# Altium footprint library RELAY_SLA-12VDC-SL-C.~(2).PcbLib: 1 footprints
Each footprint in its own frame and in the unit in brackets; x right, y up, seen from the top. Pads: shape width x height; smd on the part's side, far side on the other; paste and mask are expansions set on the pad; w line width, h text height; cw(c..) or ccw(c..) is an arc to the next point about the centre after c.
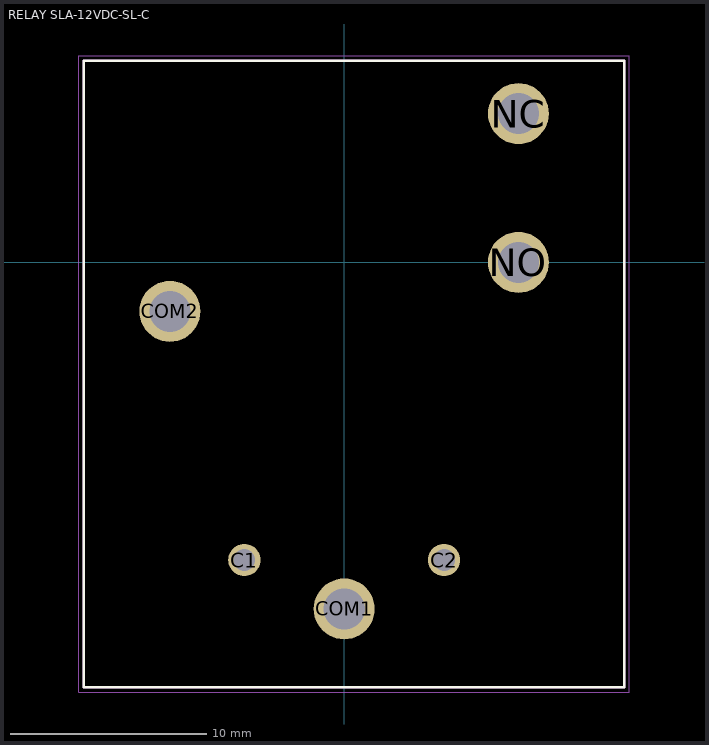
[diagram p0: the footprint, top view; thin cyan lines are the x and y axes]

## RELAY SLA-12VDC-SL-C [mm]
height 20.4
pads (6):
  round 1.65 hole 1.1: C1(-5.1,-15.2) C2(5.1,-15.2)
  round 3.116 hole 2.1: COM1(0,-17.7) COM2(-8.9,-2.5) NC(8.9,7.6) NO(8.9,0)
Top Overlay:
  lines w0.127: -13.3,-21.7 -13.3,10.3 14.3,10.3 14.3,-21.7 -13.3,-21.7
Assembly Top:
  lines w0.127: -13.3,-21.7 -13.3,10.3 14.3,10.3 14.3,-21.7 -13.3,-21.7
Courtyard Top:
  lines w0.05: -13.55,-21.95 -13.55,10.55 14.55,10.55 14.55,-21.95 -13.55,-21.95
3D body "step_temp.STEP": height 20.4, standoff -3.2, extent -13.3,-21.7 14.3,10.3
